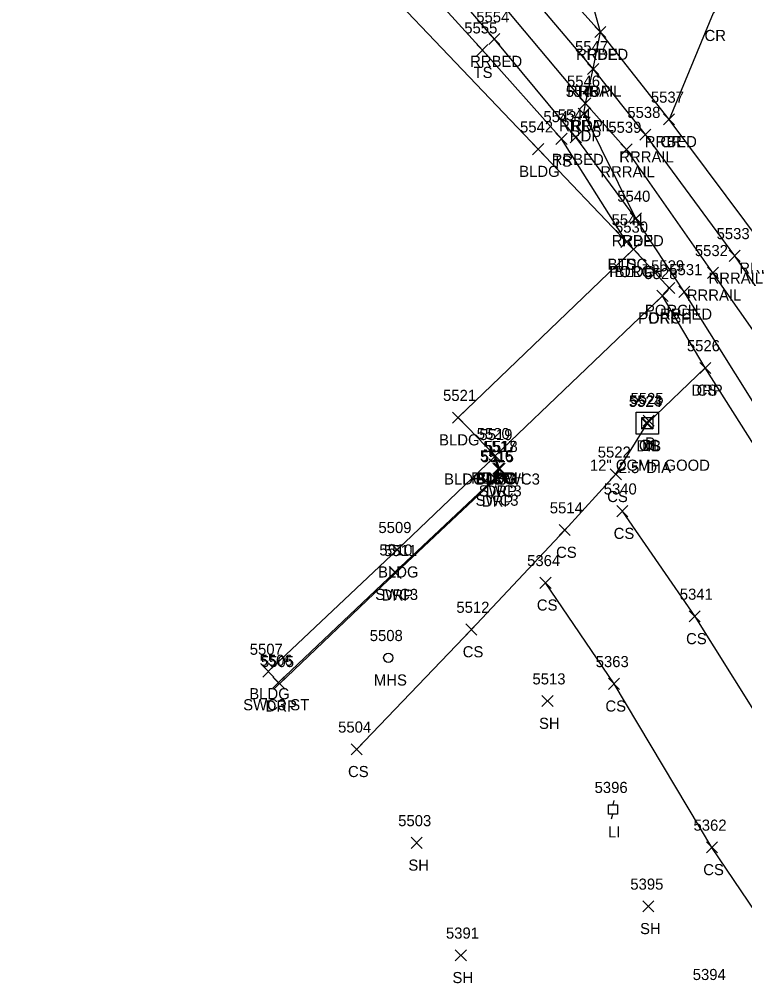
# Model space of a CAD drawing. Extents: x 1618146 to 1620418, y 640749 to 641927.
# Drawn here: x 1620088.9 to 1620219.4, y 640963.2 to 641136.7 of the extents above; entities that cross this region are included whole.
import ezdxf

# ---------------------------------------------------------------- set-up
doc = ezdxf.new("R2010")
doc.units = 0
for name, color, linetype in [('D_A', 7, 'Continuous'), ('D_C', 7, 'Continuous'), ('D_I', 7, 'Continuous'), ('D_TIC', 7, 'Continuous'), ('DS', 7, 'Continuous'), ('L_A', 7, 'Continuous'), ('L_I', 7, 'Continuous'), ('L_TIC', 7, 'Continuous'), ('LBC', 7, 'Continuous'), ('LBF', 7, 'Continuous'), ('LELB', 7, 'Continuous'), ('P_A', 7, 'Continuous'), ('P_I', 7, 'Continuous'), ('P_TIC', 7, 'Continuous'), ('PET', 7, 'Continuous'), ('PRC', 7, 'Continuous'), ('R_A', 7, 'Continuous'), ('R_I', 7, 'Continuous'), ('R_TIC', 7, 'Continuous'), ('RDP', 7, 'Continuous'), ('RR', 7, 'Continuous'), ('RRB', 7, 'Continuous'), ('RSW', 7, 'Continuous'), ('U_A', 7, 'Continuous'), ('U_I', 7, 'Continuous'), ('ULP', 7, 'Continuous'), ('USMH', 7, 'Continuous')]:
    doc.layers.add(name, color=color, linetype=linetype)

msp = doc.modelspace()

# ---------------------------------------------------------------- linework, layer by layer
at = {"layer": 'D_TIC'}
for points in [[(1620200.83, 641062.97), (1620202.83, 641064.97)], [(1620202.83, 641062.97), (1620200.83, 641064.97)], [(1620201.13, 641063.49), (1620203.13, 641065.49)], [(1620203.13, 641063.49), (1620201.13, 641065.49)]]:
    msp.add_lwpolyline(points, dxfattribs=at)
at = {"layer": 'DS'}
for p, q in [((1620199.92, 641066.06), (1620203.92, 641066.06)), ((1620199.92, 641062.06), (1620199.92, 641066.06)), ((1620203.92, 641066.06), (1620203.92, 641062.06)), ((1620200.92, 641063.06), (1620200.92, 641065.06)), ((1620200.92, 641065.06), (1620202.92, 641065.06)), ((1620201.93, 641064.06), (1620201.93, 641064.06)), ((1620201.93, 641064.06), (1620201.93, 641064.06)), ((1620202.92, 641065.06), (1620202.92, 641063.06)), ((1620202.92, 641063.06), (1620200.92, 641063.06)), ((1620203.92, 641062.06), (1620199.92, 641062.06))]:
    msp.add_line(p, q, dxfattribs=at)
at = {"layer": 'L_TIC'}
for points in [[(1620171.22, 641130.17), (1620173.22, 641132.17)], [(1620173.22, 641130.17), (1620171.22, 641132.17)], [(1620185.46, 641114.21), (1620187.46, 641116.21)], [(1620187.46, 641114.21), (1620185.46, 641116.21)], [(1620181.25, 641112.36), (1620183.25, 641114.36)], [(1620183.25, 641112.36), (1620181.25, 641114.36)], [(1620181.25, 641112.36), (1620183.25, 641114.36)], [(1620183.25, 641112.36), (1620181.25, 641114.36)], [(1620197.16, 641095.65), (1620199.16, 641097.65)], [(1620199.16, 641095.65), (1620197.16, 641097.65)], [(1620197.16, 641095.65), (1620199.16, 641097.65)], [(1620199.16, 641095.65), (1620197.16, 641097.65)], [(1620198.42, 641094.33), (1620200.42, 641096.33)], [(1620200.42, 641094.33), (1620198.42, 641096.33)], [(1620198.42, 641094.33), (1620200.42, 641096.33)], [(1620200.42, 641094.33), (1620198.42, 641096.33)], [(1620204.85, 641087.36), (1620206.85, 641089.36)], [(1620206.85, 641087.36), (1620204.85, 641089.36)], [(1620203.63, 641085.97), (1620205.63, 641087.97)], [(1620205.63, 641085.97), (1620203.63, 641087.97)], [(1620211.33, 641072.99), (1620213.33, 641074.99)], [(1620213.33, 641072.99), (1620211.33, 641074.99)], [(1620166.84, 641064.05), (1620168.84, 641066.05)], [(1620168.84, 641064.05), (1620166.84, 641066.05)], [(1620200.93, 641063.06), (1620202.93, 641065.06)], [(1620202.93, 641063.06), (1620200.93, 641065.06)], [(1620173.38, 641057), (1620175.38, 641059)], [(1620175.38, 641057), (1620173.38, 641059)], [(1620173.55, 641057.18), (1620175.55, 641059.18)], [(1620175.55, 641057.18), (1620173.55, 641059.18)], [(1620173.55, 641057.18), (1620175.55, 641059.18)], [(1620175.55, 641057.18), (1620173.55, 641059.18)], [(1620195.24, 641053.85), (1620197.24, 641055.85)], [(1620197.24, 641053.85), (1620195.24, 641055.85)], [(1620196.4, 641047.22), (1620198.4, 641049.22)], [(1620198.4, 641047.22), (1620196.4, 641049.22)], [(1620196.4, 641047.22), (1620198.4, 641049.22)], [(1620198.4, 641047.22), (1620196.4, 641049.22)], [(1620186.04, 641043.82), (1620188.04, 641045.82)], [(1620188.04, 641043.82), (1620186.04, 641045.82)], [(1620155.86, 641040.28), (1620157.86, 641042.28)], [(1620157.86, 641040.28), (1620155.86, 641042.28)], [(1620182.58, 641034.33), (1620184.58, 641036.33)], [(1620184.58, 641034.33), (1620182.58, 641036.33)], [(1620209.43, 641028.28), (1620211.43, 641030.28)], [(1620211.43, 641028.28), (1620209.43, 641030.28)], [(1620169.24, 641025.92), (1620171.24, 641027.92)], [(1620171.24, 641025.92), (1620169.24, 641027.92)], [(1620132.69, 641018.37), (1620134.69, 641020.37)], [(1620134.69, 641018.37), (1620132.69, 641020.37)], [(1620194.92, 641016.15), (1620196.92, 641018.15)], [(1620196.92, 641016.15), (1620194.92, 641018.15)], [(1620182.93, 641013.04), (1620184.93, 641015.04)], [(1620184.93, 641013.04), (1620182.93, 641015.04)], [(1620148.6, 641004.37), (1620150.6, 641006.37)], [(1620150.6, 641004.37), (1620148.6, 641006.37)], [(1620159.41, 640987.53), (1620161.41, 640989.53)], [(1620161.41, 640987.53), (1620159.41, 640989.53)], [(1620212.52, 640986.72), (1620214.52, 640988.72)], [(1620214.52, 640986.72), (1620212.52, 640988.72)], [(1620201.1, 640976.11), (1620203.1, 640978.11)], [(1620203.1, 640976.11), (1620201.1, 640978.11)], [(1620167.35, 640967.3), (1620169.35, 640969.3)], [(1620169.35, 640967.3), (1620167.35, 640969.3)]]:
    msp.add_lwpolyline(points, dxfattribs=at)
at = {"layer": 'LBC'}
for points in [[(1620182.25, 641113.36), (1620138.87, 641158.88), (1620119.63, 641179.08), (1620099.14, 641200.68), (1620061.44, 641164.75), (1620044.43, 641182.84), (1620044.17, 641182.77), (1620022.6, 641162.29), (1620014.93, 641155.19), (1620024.72, 641144.88), (1620017.73, 641138.11), (1620002.99, 641123.9), (1620002.58, 641122.32), (1620005.73, 641115.22)], [(1620133.69, 641019.37), (1620156.86, 641041.28), (1620174.38, 641058), (1620174.55, 641058.18), (1620167.84, 641065.05), (1620199.42, 641095.33), (1620198.16, 641096.65), (1620182.25, 641113.36)]]:
    msp.add_lwpolyline(points, dxfattribs=at)
at = {"layer": 'LBF'}
msp.add_lwpolyline([(1620174.55, 641058.18), (1620204.63, 641086.97), (1620205.85, 641088.36), (1620199.42, 641095.33)], dxfattribs=at)
at = {"layer": 'LELB'}
for points in [[(1620198.16, 641096.65), (1620186.46, 641115.21), (1620172.22, 641131.17), (1620143.87, 641162.38), (1620123.75, 641182.71), (1620104.93, 641199.85), (1620097.93, 641205.84), (1620094.19, 641209.35)], [(1620149.6, 641005.37), (1620170.24, 641026.92), (1620187.04, 641044.82), (1620196.24, 641054.85), (1620201.93, 641064.06), (1620212.33, 641073.99)], [(1620197.4, 641048.22), (1620210.43, 641029.28), (1620224.45, 641006.96), (1620238.86, 640984.1), (1620252.72, 640965.56)], [(1620233.64, 640957.47), (1620224.05, 640972.09), (1620213.52, 640987.72), (1620195.92, 641017.15), (1620183.58, 641035.33)]]:
    msp.add_lwpolyline(points, dxfattribs=at)
at = {"layer": 'P_TIC'}
for points in [[(1620192.46, 641133.42), (1620194.46, 641135.42)], [(1620194.46, 641133.42), (1620192.46, 641135.42)], [(1620191.15, 641126.79), (1620193.15, 641128.79)], [(1620193.15, 641126.79), (1620191.15, 641128.79)], [(1620189.75, 641120.59), (1620191.75, 641122.59)], [(1620191.75, 641120.59), (1620189.75, 641122.59)], [(1620189.48, 641118.75), (1620191.48, 641120.75)], [(1620191.48, 641118.75), (1620189.48, 641120.75)], [(1620204.8, 641117.71), (1620206.8, 641119.71)], [(1620206.8, 641117.71), (1620204.8, 641119.71)], [(1620198.84, 641099.89), (1620200.84, 641101.89)], [(1620200.84, 641099.89), (1620198.84, 641101.89)]]:
    msp.add_lwpolyline(points, dxfattribs=at)
at = {"layer": 'PET'}
msp.add_lwpolyline([(1620199.84, 641100.89), (1620190.48, 641119.75), (1620190.75, 641121.59), (1620192.15, 641127.79), (1620193.46, 641134.42), (1620190.67, 641144.59), (1620174.45, 641161.94), (1620160.08, 641178.42), (1620147.25, 641189.39)], dxfattribs=at)
at = {"layer": 'PRC'}
msp.add_lwpolyline([(1620256.84, 641199.42), (1620250.09, 641183.97), (1620236.84, 641166.4), (1620223.56, 641150.86), (1620213.75, 641137.81), (1620205.8, 641118.71)], dxfattribs=at)
at = {"layer": 'R_TIC'}
for points in [[(1620192.46, 641133.42), (1620194.46, 641135.42)], [(1620194.46, 641133.42), (1620192.46, 641135.42)], [(1620173.38, 641132.16), (1620175.38, 641134.16)], [(1620175.38, 641132.16), (1620173.38, 641134.16)], [(1620191.15, 641126.79), (1620193.15, 641128.79)], [(1620193.15, 641126.79), (1620191.15, 641128.79)], [(1620189.75, 641120.59), (1620191.75, 641122.59)], [(1620191.75, 641120.59), (1620189.75, 641122.59)], [(1620204.8, 641117.71), (1620206.8, 641119.71)], [(1620206.8, 641117.71), (1620204.8, 641119.71)], [(1620188.04, 641114.52), (1620190.04, 641116.52)], [(1620190.04, 641114.52), (1620188.04, 641116.52)], [(1620200.56, 641114.97), (1620202.56, 641116.97)], [(1620202.56, 641114.97), (1620200.56, 641116.97)], [(1620197.15, 641112.29), (1620199.15, 641114.29)], [(1620199.15, 641112.29), (1620197.15, 641114.29)], [(1620198.84, 641099.89), (1620200.84, 641101.89)], [(1620200.84, 641099.89), (1620198.84, 641101.89)], [(1620216.62, 641093.16), (1620218.62, 641095.16)], [(1620218.62, 641093.16), (1620216.62, 641095.16)], [(1620212.71, 641090.11), (1620214.71, 641092.11)], [(1620214.71, 641090.11), (1620212.71, 641092.11)], [(1620207.55, 641086.68), (1620209.55, 641088.68)], [(1620209.55, 641086.68), (1620207.55, 641088.68)], [(1620203.63, 641085.97), (1620205.63, 641087.97)], [(1620205.63, 641085.97), (1620203.63, 641087.97)], [(1620211.33, 641072.99), (1620213.33, 641074.99)], [(1620213.33, 641072.99), (1620211.33, 641074.99)], [(1620173.38, 641057), (1620175.38, 641059)], [(1620175.38, 641057), (1620173.38, 641059)], [(1620173.55, 641057.18), (1620175.55, 641059.18)], [(1620175.55, 641057.18), (1620173.55, 641059.18)], [(1620174.09, 641054.87), (1620176.09, 641056.87)], [(1620176.09, 641054.87), (1620174.09, 641056.87)], [(1620173.52, 641053.19), (1620175.52, 641055.19)], [(1620175.52, 641053.19), (1620173.52, 641055.19)], [(1620174.32, 641054.86), (1620176.32, 641056.86)], [(1620176.32, 641054.86), (1620174.32, 641056.86)], [(1620173.64, 641053.02), (1620175.64, 641055.02)], [(1620175.64, 641053.02), (1620173.64, 641055.02)], [(1620155.46, 641036.24), (1620157.46, 641038.24)], [(1620157.46, 641036.24), (1620155.46, 641038.24)], [(1620155.63, 641036.13), (1620157.63, 641038.13)], [(1620157.63, 641036.13), (1620155.63, 641038.13)], [(1620134.53, 641016.39), (1620136.53, 641018.39)], [(1620136.53, 641016.39), (1620134.53, 641018.39)], [(1620134.72, 641016.16), (1620136.72, 641018.16)], [(1620136.72, 641016.16), (1620134.72, 641018.16)]]:
    msp.add_lwpolyline(points, dxfattribs=at)
at = {"layer": 'RDP'}
for points in [[(1620260.97, 640976.58), (1620260.23, 640976.78), (1620258.64, 640977.67), (1620254.7, 640981.22), (1620253.56, 640984.4), (1620254.45, 640989.13), (1620259.89, 640996.41), (1620260.58, 640997.17), (1620250.83, 641012.27), (1620227.25, 641050.42), (1620212.33, 641073.99), (1620204.63, 641086.97)], [(1620135.72, 641017.16), (1620156.63, 641037.13), (1620174.64, 641054.02), (1620175.32, 641055.86), (1620174.55, 641058.18)]]:
    msp.add_lwpolyline(points, dxfattribs=at)
at = {"layer": 'RR'}
for points in [[(1620346.47, 640860.45), (1620330.76, 640897.47), (1620318, 640923.55), (1620306.67, 640947.65), (1620300.32, 640960.31), (1620293.94, 640972.26), (1620285.98, 640987.1), (1620281.46, 640995.25), (1620258.36, 641033.11), (1620241.32, 641059.63), (1620217.62, 641094.16), (1620201.56, 641115.97), (1620192.15, 641127.79), (1620168.31, 641155.99)], [(1620341.49, 640859.44), (1620326.2, 640895.4), (1620313.96, 640922.1), (1620303.21, 640943.7), (1620296.61, 640956.78), (1620290.44, 640967.96), (1620282.92, 640982.14), (1620278.2, 640990.78), (1620254.11, 641030.53), (1620237.65, 641056.89), (1620213.71, 641091.11), (1620198.15, 641113.29), (1620190.75, 641121.59), (1620164.76, 641152.66)]]:
    msp.add_lwpolyline(points, dxfattribs=at)
at = {"layer": 'RRB'}
for points in [[(1620282.83, 641005.9), (1620262.96, 641036.11), (1620245.55, 641062.88), (1620222.8, 641095.96), (1620205.8, 641118.71), (1620193.46, 641134.42), (1620171.4, 641158.88), (1620156.47, 641175.88), (1620136.03, 641194.9), (1620112.95, 641215.97), (1620104.58, 641223.13), (1620095.97, 641212.17)], [(1620271.86, 640991.56), (1620248.91, 641026.87), (1620231.32, 641051.3), (1620208.55, 641087.68), (1620199.84, 641100.89), (1620189.04, 641115.52), (1620174.38, 641133.16), (1620146.78, 641165.45), (1620126.45, 641185.25), (1620103.32, 641205.3), (1620095.97, 641212.17)]]:
    msp.add_lwpolyline(points, dxfattribs=at)
at = {"layer": 'RSW'}
msp.add_lwpolyline([(1620135.53, 641017.39), (1620156.46, 641037.24), (1620174.52, 641054.19), (1620175.09, 641055.87), (1620174.38, 641058)], dxfattribs=at)
at = {"layer": 'ULP'}
for p, q in [((1620195.89, 640996.18), (1620195.72, 640995.35)), ((1620194.89, 640993.68), (1620194.89, 640995.35)), ((1620194.89, 640995.35), (1620196.56, 640995.35)), ((1620195.72, 640994.51), (1620195.72, 640994.51)), ((1620196.56, 640995.35), (1620196.56, 640993.68)), ((1620196.56, 640993.68), (1620194.89, 640993.68)), ((1620195.47, 640992.85), (1620195.72, 640993.68))]:
    msp.add_line(p, q, dxfattribs=at)
at = {"layer": 'USMH'}
for p, q in [((1620155.29, 641021.84), (1620155.29, 641021.84)), ((1620156.12, 641021.84), (1620156.12, 641021.84))]:
    msp.add_line(p, q, dxfattribs=at)
msp.add_circle((1620155.29, 641021.84), 0.833, dxfattribs=at)

# ---------------------------------------------------------------- texts
at = {"layer": 'D_A'}
for s, p in [('DIB', (1620199.93, 641058.97)), ('DI', (1620200.98, 641059.06)), ('P', (1620201.51, 641059.49))]:
    msp.add_text(s, height=2, dxfattribs=at).set_placement(p)
at = {"layer": 'D_C'}
for s, p in [('12" CGMP GOOD', (1620191.56, 641055.49)), ("2.5' DIA", (1620196.74, 641055.06))]:
    msp.add_text(s, height=2, dxfattribs=at).set_placement(p)
at = {"layer": 'D_I'}
for s, p in [('5523', (1620198.67, 641067.06)), ('5525', (1620198.87, 641067.49)), ('5524', (1620198.57, 641066.97))]:
    msp.add_text(s, height=2, dxfattribs=at).set_placement(p)
at = {"layer": 'L_A'}
for s, p in [('TS', (1620170.63, 641126.17)), ('TS', (1620184.87, 641110.21)), ('BLDG', (1620178.84, 641108.36)), ('BLDG', (1620178.84, 641108.36)), ('BLDG', (1620194.75, 641091.65)), ('TS', (1620196.57, 641091.65)), ('PORCH', (1620195.05, 641090.33)), ('BLDG', (1620196.01, 641090.33)), ('PORCH', (1620201.47, 641083.36)), ('PORCH', (1620200.25, 641081.97)), ('CS', (1620210.77, 641068.99)), ('BLDG', (1620164.43, 641060.05)), ('CS', (1620200.37, 641059.06)), ('PORCH', (1620170.17, 641053.18)), ('BLDG', (1620171.14, 641053.18)), ('BLDG', (1620170.98, 641053)), ('CS', (1620194.68, 641049.85)), ('CS', (1620195.84, 641043.22)), ('CS', (1620195.84, 641043.22)), ('CS', (1620185.48, 641039.82)), ('BLDG', (1620153.45, 641036.28)), ('CS', (1620182.02, 641030.33)), ('CS', (1620208.87, 641024.28)), ('CS', (1620168.68, 641021.92)), ('BLDG', (1620130.28, 641014.37)), ('CS', (1620194.36, 641012.15)), ('SH', (1620182.41, 641009.04)), ('CS', (1620148.04, 641000.37)), ('SH', (1620158.9, 640983.53)), ('CS', (1620211.96, 640982.72)), ('SH', (1620200.59, 640972.11)), ('SH', (1620166.84, 640963.3))]:
    msp.add_text(s, height=2, dxfattribs=at).set_placement(p)
at = {"layer": 'L_I'}
for s, p in [('5555', (1620168.96, 641134.17)), ('5543', (1620183.2, 641118.21)), ('5542', (1620178.99, 641116.36)), ('5542', (1620178.99, 641116.36)), ('5541', (1620195.47, 641099.65)), ('5541', (1620195.47, 641099.65)), ('5530', (1620196.08, 641098.33)), ('5530', (1620196.08, 641098.33)), ('5529', (1620202.58, 641091.36)), ('5528', (1620201.37, 641089.97)), ('5526', (1620209.02, 641076.99)), ('5521', (1620165.14, 641068.05)), ('5523', (1620198.67, 641067.06)), ('5520', (1620171.2, 641061.18)), ('5520', (1620171.2, 641061.18)), ('5519', (1620171.68, 641061)), ('5522', (1620192.98, 641057.85)), ('5340', (1620194.05, 641051.22)), ('5340', (1620194.05, 641051.22)), ('5514', (1620184.35, 641047.82)), ('5509', (1620153.51, 641044.28)), ('5364', (1620180.27, 641038.33)), ('5341', (1620207.74, 641032.28)), ('5512', (1620167.54, 641029.92)), ('5507', (1620130.36, 641022.37)), ('5363', (1620192.61, 641020.15)), ('5513', (1620181.23, 641017.04)), ('5504', (1620146.26, 641008.37)), ('5503', (1620157.07, 640991.53)), ('5362', (1620210.21, 640990.72)), ('5395', (1620198.84, 640980.11)), ('5391', (1620165.66, 640971.3)), ('5394', (1620210.07, 640963.85))]:
    msp.add_text(s, height=2, dxfattribs=at).set_placement(p)
at = {"layer": 'P_A'}
for s, p in [('CR', (1620212.19, 641132.81)), ('RDP', (1620190.95, 641129.42)), ('RDP', (1620189.64, 641122.79)), ('RDP', (1620188.24, 641116.59)), ('RDP', (1620187.96, 641114.75)), ('CR', (1620204.24, 641113.71)), ('RDP', (1620197.33, 641095.89))]:
    msp.add_text(s, height=2, dxfattribs=at).set_placement(p)
at = {"layer": 'P_I'}
for s, p in [('5547', (1620188.89, 641130.79)), ('5546', (1620187.44, 641124.59)), ('5545', (1620187.22, 641122.75)), ('5537', (1620202.54, 641121.71)), ('5540', (1620196.49, 641103.89))]:
    msp.add_text(s, height=2, dxfattribs=at).set_placement(p)
at = {"layer": 'R_A'}
for s, p in [('RRBED', (1620170.02, 641128.16)), ('RRBED', (1620189.1, 641129.42)), ('RRRAIL', (1620187.44, 641122.79)), ('RRRAIL', (1620186.04, 641116.59)), ('RRBED', (1620201.45, 641113.71)), ('RRBED', (1620184.69, 641110.52)), ('RRRAIL', (1620196.85, 641110.97)), ('RRRAIL', (1620193.44, 641108.29)), ('RRBED', (1620195.49, 641095.89)), ('RRBED', (1620218.45, 641090.96)), ('RRRAIL', (1620212.91, 641089.16)), ('RRRAIL', (1620209, 641086.11)), ('RRBED', (1620204.19, 641082.68)), ('DRP', (1620202.12, 641081.97)), ('DRP', (1620209.82, 641068.99)), ('DRP', (1620172.03, 641053.18)), ('BLDG4 SWC3', (1620165.33, 641053)), ('SWC3', (1620171.56, 641050.87)), ('DRP', (1620172.81, 641050.86)), ('SWC3', (1620171, 641049.19)), ('DRP', (1620172.13, 641049.02)), ('SWC3', (1620152.93, 641032.24)), ('DRP', (1620154.12, 641032.13)), ('SWC3 ST', (1620129.18, 641012.39)), ('DRP', (1620133.21, 641012.16))]:
    msp.add_text(s, height=2, dxfattribs=at).set_placement(p)
at = {"layer": 'R_I'}
for s, p in [('5554', (1620171.12, 641136.16)), ('5547', (1620188.89, 641130.79)), ('5546', (1620187.44, 641124.59)), ('5537', (1620202.54, 641121.71)), ('5544', (1620185.78, 641118.52)), ('5538', (1620198.3, 641118.97)), ('5539', (1620194.88, 641116.29)), ('5540', (1620196.49, 641103.89)), ('5533', (1620214.36, 641097.16)), ('5532', (1620210.45, 641094.11)), ('5528', (1620201.37, 641089.97)), ('5531', (1620205.85, 641090.68)), ('5526', (1620209.02, 641076.99)), ('5520', (1620171.2, 641061.18)), ('5519', (1620171.68, 641061)), ('5517', (1620172.39, 641058.87)), ('5518', (1620172.63, 641058.86)), ('5516', (1620171.78, 641057.19)), ('5515', (1620171.94, 641057.02)), ('5510', (1620153.68, 641040.24)), ('5511', (1620154.51, 641040.13)), ('5506', (1620132.14, 641020.39)), ('5505', (1620132.38, 641020.16))]:
    msp.add_text(s, height=2, dxfattribs=at).set_placement(p)
at = {"layer": 'U_A'}
for s, p in [('MHS', (1620152.7, 641016.84)), ('LI', (1620194.83, 640989.51))]:
    msp.add_text(s, height=2, dxfattribs=at).set_placement(p)
at = {"layer": 'U_I'}
for s, p in [('5508', (1620151.95, 641024.84)), ('5396', (1620192.41, 640997.51))]:
    msp.add_text(s, height=2, dxfattribs=at).set_placement(p)

doc.saveas('drawing.dxf')
